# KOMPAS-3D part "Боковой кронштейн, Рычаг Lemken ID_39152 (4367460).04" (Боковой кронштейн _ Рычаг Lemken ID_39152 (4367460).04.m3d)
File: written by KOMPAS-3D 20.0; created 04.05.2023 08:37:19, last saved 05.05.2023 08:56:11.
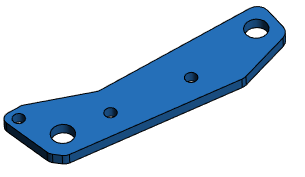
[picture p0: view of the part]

Document properties: Автор: factory; Полное имя файла: C:\Users\factory\Desktop\Чертежи\Рычаг Lemken ID_39152 (4367460)\Боковой кронштейн _ Рычаг Lemken ID_39152 (4367460).04.m3d

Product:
- Part/product: Боковой кронштейн  | designation Рычаг Lemken ID_39152 (4367460).04
    Материал: Лист$d32х1700х4200 ГОСТ 19903-2015;295-09Г2-ГС ГОСТ 19281-2014$ (density 7850 kg/m3)
    Масса: 23.1903

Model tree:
1. Эскиз:1
2. Элемент выдавливания:1
     Расстояние 1 = 30

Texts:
  Рычаг Lemken ID_39152 (4367460).04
